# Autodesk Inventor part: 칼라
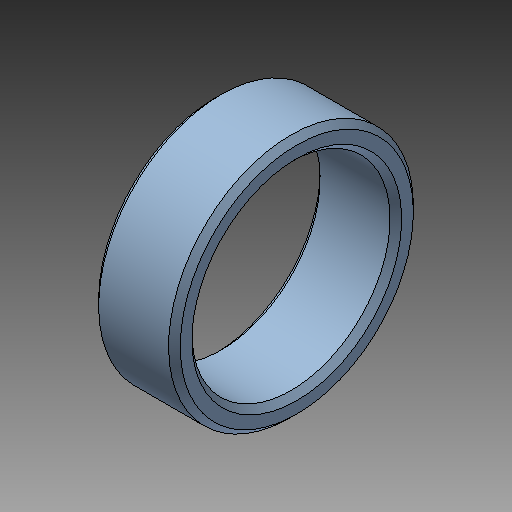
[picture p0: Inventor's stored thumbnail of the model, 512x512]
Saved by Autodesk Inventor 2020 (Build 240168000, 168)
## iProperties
Created: 2024-01
Part Number: 칼라
Material: 강철, 합금
Document SubType Name: Modeling
Designer: mdu-01
Density: 1 g/cm^3
Appearance: 기본값(1)
Author: mdu-01
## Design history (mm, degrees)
sketch "스케치1"
  geometry: L1 (-3.5, 0)-(3.5, 0); L2 (-3, 8.5)-(3, 8.5); L3 (3.5, 9)-(3.5, 10); L4 (3, 10.5)-(-3, 10.5); L5 (-3.5, 10)-(-3.5, 9); L6 (-3, 10.5)-(-3.5, 10); L7 (-3, 8.5)-(-3.5, 9); L8 (3, 8.5)-(3.5, 9); L9 (3.5, 10)-(3, 10.5); 6 further points
  constraints: 18 end point, 10 point on line, 2 horizontal, 2 parallel, 1 coincident, 1 midpoint, 1 perpendicular
  dimensions: "d0" = 7 distance of L1.start L1.end; "d1" = 17 diameter of L2 L1; "d2" = 2 distance between parallel lines of L4 L2; "d3" = 0.5 distance of L4.end point (-3.5, 10.5); "d4" = 0.5 distance of L5.start point (-3.5, 10.5) (= d3); "d5" = 0.5 distance of L2.start point (-3.5, 8.5) (= d3); "d6" = 0.5 distance of L5.end point (-3.5, 8.5) (= d5); "d7" = 0.5 distance of L2.end point (3.5, 8.5) (= d3); "d8" = 0.5 distance of L3.start point (3.5, 8.5) (= d7); "d9" = 0.5 distance of L3.end point (3.5, 10.5) (= d3); "d10" = 0.5 distance of L4.start point (3.5, 10.5) (= d9)
revolve "회전1" sketch "스케치1" stored, may be unused: angle "d11" = 90 deg
node "솔리드1"
